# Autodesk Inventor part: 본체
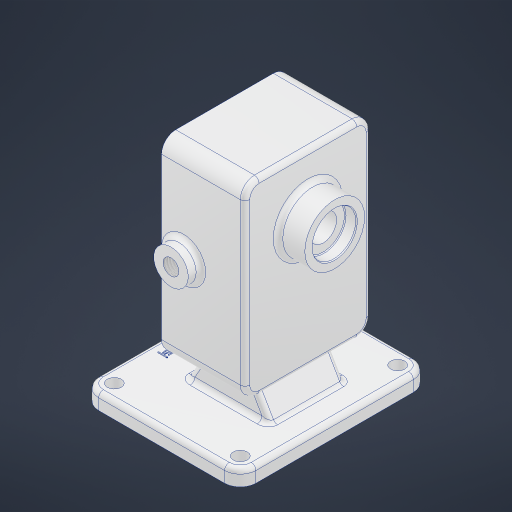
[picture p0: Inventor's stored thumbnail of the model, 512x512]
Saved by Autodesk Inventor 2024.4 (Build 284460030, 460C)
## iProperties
Created: 2026-10
Part Number: 본체
Material: 알루미늄 6061
Document SubType Name: Modeling
Designer: user
Density: 2.7 g/cm^3
Appearance: 알루미늄 - 평지
Mass: 1469.29 g
Surface Area: 819.998 cm^2
Volume: 544.181 cm^3
Author: user
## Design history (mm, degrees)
sketch "스케치1"
  geometry: L1 (50, 60)-(-50, 60); L2 (-50, 60)-(-50, -60); L3 (-50, -60)-(50, -60); L4 (50, -60)-(50, 60); L5 (50, 60)-(-50, -60); L6 (-50, 60)-(50, -60); 1 further point
  constraints: 12 end point, 2 midpoint, 2 parallel, 1 horizontal, 1 perpendicular
  dimensions: "d0" = 100 distance of L3.end L2.end; "d1" = 120 distance of L2.end L1.end
extrude "돌출1" new body sketch "스케치1" distance "d2" = 10; taper "d3" = 0 deg
fillet "모깎기1" dims "d4" = 10
sketch "스케치2"
  geometry: A1 r 10 centre (40, -50) between (40, -60) and (50, -50) reference; A2 r 10 centre (40, 50) between (50, 50) and (40, 60) reference; A3 r 10 centre (-40, 50) between (-40, 60) and (-50, 50) reference; A4 r 10 centre (-40, -50) between (-50, -50) and (-40, -60) reference; 5 further points
  constraints: 4 coincident
hole "구멍1" sketch "스케치2" at (-40, 50), (40, 50), (40, -50), (-40, -50) diameter "d5" = 9; stored, may be unused: countersink angle "d9" = 90 deg, drill point angle "d11" = 118 deg; dims "d6" = 6, "d7" = 4, "d8" = 2, "d10" = 8
fillet "모깎기2" dims "d12" = 3
sketch "스케치3"
  geometry: L1 (-40, 10)-(40, 10) reference; L2 (-20, 10)-(-8.453, 30); L3 (-8.453, 30)-(21.453, 30); L4 (21.453, 30)-(33, 10); L5 (50, 7)-(50, 0) reference; 1 further point
  constraints: 6 end point, 2 point on line, 1 parallel
  dimensions: "d13" = 17 distance from line of L5 L4.end; "d14" = 60 deg angle of L1 L2 (= d15); "d15" = 60 deg angle of L1 L4; "d16" = 53 distance of L4.end L2.start; "d17" = 20 distance between parallel lines of L3 L1
extrude "돌출2" join sketch "스케치3" stored distance "d18" = 48; taper "d19" = 0 deg
sketch "스케치4"
  geometry: L1 (0, 0)-(0, 48) reference; L2 (29.906, 0)-(0, 0) reference; L3 (29.906, 48)-(29.906, 0) reference; L4 (0, 48)-(29.906, 48) reference; L5 (-11.547, 64)-(41.453, 64); L6 (41.453, 64)-(41.453, -16); L7 (41.453, -16)-(-11.547, -16); L8 (-11.547, -16)-(-11.547, 64); L9 (-11.547, 0)-(-11.547, 48) reference; 2 further points
  constraints: 8 end point, 2 midpoint, 2 parallel, 1 horizontal, 1 perpendicular
  dimensions: "d20" = 53 distance of L6.end L7.end; "d21" = 80 distance of L5.end L6.end
extrude "돌출3" join sketch "스케치4" distance "d22" = 120; taper "d23" = 0 deg
sketch "스케치5"
  geometry: L1 (0, 120)-(80, 120) reference; L2 (0, 0)-(0, 120) reference; L3 (40, 82)-(40, 38); L4 (16, 82)-(16, 38); L5 (64, 38)-(64, 82); A1 r 24 centre (40, 82) between (64, 82) and (16, 82); A2 r 24 centre (40, 38) between (16, 38) and (64, 38); 6 further points
  constraints: 8 end point, 5 point on circle, 4 midpoint, 4 tangent, 2 centre point, 1 horizontal alignment, 1 parallel, 1 vertical, 1 vertical alignment
  dimensions: "d25" = 24 radius of A1; "d26" = 44 distance of L3.start L3.end
extrude "돌출4" cut sketch "스케치5" distance "d27" = 29; taper "d28" = 0 deg
sketch "스케치6"
  geometry: L1 (0, 0)-(80, 0) reference; L2 (80, 0)-(80, 120) reference; 9 further points
  constraints: 6 vertical alignment, 4 horizontal alignment
  dimensions: "d29" = 62 distance of point (71, 111) point (9, 111); "d30" = 29 distance of point (71, 82) point (71, 111); "d31" = 44 distance of point (71, 38) point (71, 82); "d32" = 29 distance of point (71, 9) point (71, 38) (= d30); "d33" = 9 distance from line of L2 point (71, 9); "d34" = 9 distance from line of L1 point (71, 9) (computed from d32, d30, d31)
hole "구멍2" sketch "스케치6" at (9, 111), (71, 111), (71, 82), (9, 82), (9, 38), (71, 38), (71, 9), (9, 9) diameter "d35" = 4.134; stored, may be unused: countersink angle "d39" = 90 deg, drill point angle "d41" = 118 deg; dims "d36" = 10, "d37" = 4, "d38" = 2, "d40" = 12
fillet "모깎기3" dims "d42" = 9
fillet "모깎기4" dims "d43" = 3
sketch "스케치7"
  geometry: C1 r 12.5 at (40, 82); C2 r 12.5 at (40, 38); A1 r 24 centre (40, 38) between (16, 38) and (64, 38) reference; A2 r 24 centre (40, 82) between (64, 82) and (16, 82) reference; 1 further point
  constraints: 2 centre point, 2 coincident
  dimensions: "d44" = 25 diameter of C1; "d45" = 25 diameter of C2
extrude "돌출5" cut sketch "스케치7" distance "d46" = 15; taper "d47" = 0 deg
sketch "스케치8"
  geometry: C1 r 12.5 at (0, 0) reference; C2 r 8.5 at (0, 0); 1 further point
  constraints: 1 centre point, 1 coincident
  dimensions: "d48" = 17 diameter of C2
extrude "돌출6" cut sketch "스케치8" extent not by distance; stored distance "d49" = 0; taper "d50" = 0 deg
sketch "스케치9"
  geometry: C1 r 8.5 at (37, 73) reference; C2 r 19 at (37, 73); 1 further point
  constraints: 1 centre point, 1 coincident
  dimensions: "d51" = 38 diameter of C2
extrude "돌출7" join sketch "스케치9" distance "d52" = 17; taper "d53" = 0 deg
sketch "스케치10"
  geometry: C1 r 8.5 at (0, 0) reference; C2 r 14 at (0, 0); 1 further point
  constraints: 1 centre point, 1 coincident
  dimensions: "d54" = 28 diameter of C2
extrude "돌출8" cut sketch "스케치10" distance "d55" = 7.3; taper "d56" = 0 deg
sketch "스케치11"
  geometry: L1 (0, 0)-(0, 102) reference; C1 r 11 at (14, 51); 2 further points
  constraints: 1 centre point, 1 horizontal alignment, 1 midpoint
  dimensions: "d57" = 22 diameter of C1; "d58" = 14 distance from line of C1.centre L1
extrude "돌출9" join sketch "스케치11" distance "d59" = 8; taper "d60" = 0 deg
sketch "스케치12"
  geometry: C1 r 11 at (0, 0) reference; 2 further points
  constraints: 1 coincident
sketch "스케치13"
  geometry: C1 r 11 at (0, 0) reference; 2 further points
  constraints: 1 coincident
hole "구멍3" sketch "스케치12" diameter "d61" = 10.106; stored, may be unused: countersink angle "d65" = 90 deg, drill point angle "d67" = 118 deg; dims "d62" = 8, "d63" = 4, "d64" = 2, "d66" = 32.3
hole "구멍4" sketch "스케치13" diameter "d68" = 10.106; stored, may be unused: countersink angle "d72" = 90 deg, drill point angle "d74" = 118 deg; dims "d69" = 8, "d70" = 4, "d71" = 2, "d73" = 8
fillet "모깎기5" dims "d75" = 3
fillet "모깎기6" dims "d76" = 3
chamfer "모따기1" distance "d77" = 1; stored, may be unused: second distance "d78" = 2, angle "d79" = 45 deg
fillet "모깎기7" dims "d80" = 0.5
chamfer "모따기2" distance "d81" = 0.7; stored, may be unused: second distance "d82" = 2, angle "d83" = 30 deg
fillet "모깎기8" dims "d84" = 3
fillet "모깎기9" dims "d85" = 3
node "작업 평면1"
sketch "스케치14"
  geometry: L1 (-47, -50)-(-47, 50) reference; L2 (-34, 21)-(-34, -21); L3 (-34, -21)-(-46, -21); L4 (-46, -21)-(-46, 21); L5 (-46, 21)-(-34, 21); L6 (-50, 50)-(-50, -50) reference; A1 r 7 centre (-40, -50) between (-47, -50) and (-40, -57) reference; 5 further points
  constraints: 4 midpoint, 1 horizontal alignment, 1 vertical alignment, 2 other
  dimensions: "d86" = 10 distance from line of L6 point (-40, 21); "d88" = 12 distance of L4.end L2.start; "d89" = 42 distance of L2.start L2.end
feature "엠보싱2" sketch "스케치14" dims "d0" = 100, "d1" = 120, "d93" = 0.5, "d94" = 0
node "솔리드1"
mirror "미러1"
feature "A9D066F2-1C7D-4E18-AEED-F7BC21143FA4" dims "d5" = 9, "d6" = 6, "d7" = 4, "d8" = 2, "d9" = 90 deg, "d10" = 8, "d11" = 118 deg
other parameters: "d92" = 0.5
